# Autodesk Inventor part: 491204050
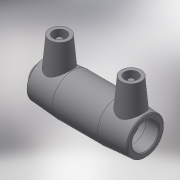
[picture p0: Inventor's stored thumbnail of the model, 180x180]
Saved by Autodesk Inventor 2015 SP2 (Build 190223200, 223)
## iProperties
Created: 2017-06
Part Number: 491204050
Material: Generic
Description: PLASSON END CAP 50
Document SubType Name: Modeling
Designer: KIM
Mass: 38.9236 g
Surface Area: 152.394 cm^2
Volume: 38.9236 cm^3
Density: 1 g/cm^3
Appearance: Default
Author: KIM
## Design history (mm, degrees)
derived "491204.ipt"
feature "Solid1::491204.ipt"
tag "TaggingFeature1"
body "Solid1"
other parameters: "d0" = 101, "d2" = 67, "d3" = 49, "d4" = 30.25, "d5" = 60.3, "d6" = 47.5, "d8" = 168 deg, "d10" = 19.6, "d11" = 6.53333, "d13" = 96.8, "d14" = 17.6296, "d15" = 49, "d16" = 49, "d17" = 47.5, "d19" = 3.52592, "d20" = 168 deg, "d22" = 62.98, "d23" = 67, "d24" = 61.0906, "d25" = 135 deg, "d26" = 43.56, "d27" = 135 deg, "d29" = 51, "d30" = 15, "d31" = 38.72, "d34" = 5 deg, "d35" = 15, "d39" = 5 deg, "d41" = 4, "d42" = 14, "d43" = 0, "d45" = 4, "d46" = 14, "d47" = 0, "d48" = 121, "d49" = 1, "d52" = 2.178, "d53" = 55, "d54" = 2.178, "d56" = 5, "d57" = 1.5, "d60" = 18.15, "d61" = 1, "d63" = 121, "d64" = 1, "d68" = 55, "d69" = 2.42, "d70" = 0, "d71" = 2.178, "d72" = 3, "d73" = 0, "d74" = 14.21, "d75" = 4.73667, "d76" = 3, "d77" = 0, "L_" = 121, "L_1" = 49, "D_" = 67, "A_" = 51, "d_2" = 12, "L_0" = 101, "d55" = 5
